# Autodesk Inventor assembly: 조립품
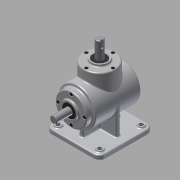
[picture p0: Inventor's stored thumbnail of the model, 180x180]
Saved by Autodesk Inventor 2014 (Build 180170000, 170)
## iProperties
Created: 2015-07
Part Number: 조립품
Document SubType Name: Assembly
Designer: L-10
Author: L-10
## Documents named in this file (14)
- C:\Users\L-10\Desktop\450706V1004\조립품.iam
- C:\Users\L-10\Desktop\450706V1004\본체.ipt
- C:\Users\L-10\Desktop\450706V1004\커버.ipt
- C:\Users\L-10\Desktop\450706V1004\베어링 6203.ipt
- C:\Users\L-10\Desktop\450706V1004\메인 축.ipt
- 메인 축.ipt
- C:\Users\L-10\Desktop\450706V1004\키 5x5.ipt
- C:\Users\L-10\Desktop\450706V1004\메인 베벨기어.ipt
- C:\Users\L-10\Desktop\450706V1004\오일실.ipt
- C:\Users\L-10\Desktop\450706V1004\서브 축.ipt
- 서브 축.ipt
- C:\Users\L-10\Desktop\450706V1004\키 4x4.ipt
- C:\Users\L-10\Desktop\450706V1004\서브 베벨기어.ipt
- C:\Users\L-10\Desktop\450706V1004\M4.ipt
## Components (8 placed, 1 different names)
1. M4:1 — 각도:1
2. M4:3
3. M4:4
4. M4:5
5. M4:2 — 각도:2
6. M4:6
7. M4:7
8. M4:8
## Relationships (2: Angle 2)
- 각도:1 [Angle]: M4:1
- 각도:2 [Angle]: M4:2
